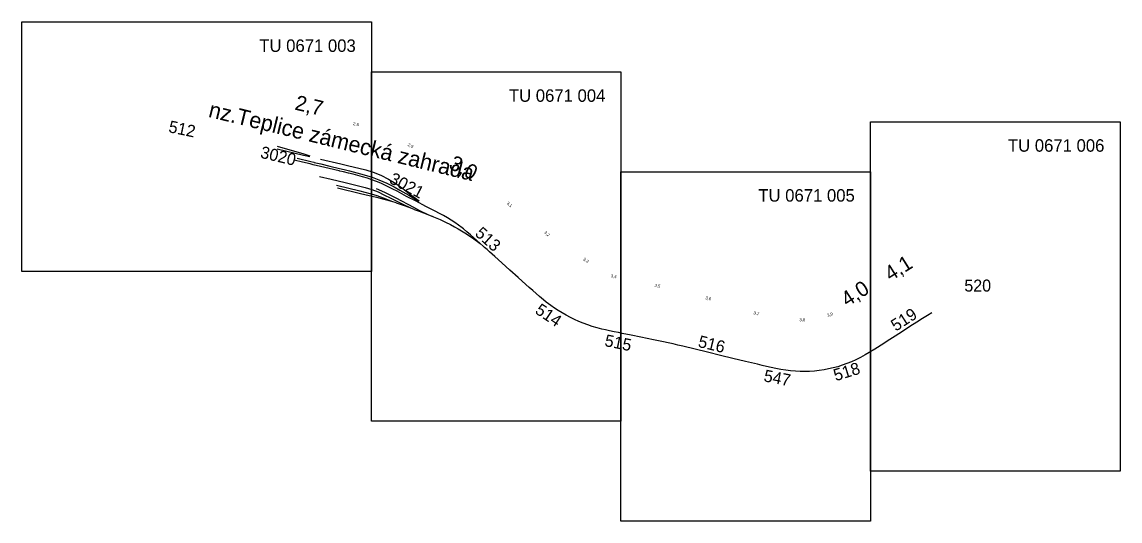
# Model space of a CAD drawing. Extents: x -777700 to -775500, y -977500 to -976500.
import ezdxf

# ---------------------------------------------------------------- set-up
doc = ezdxf.new("R2010")
doc.units = 0
for name, color, linetype in [('Vrstva 1', 7, 'Continuous'), ('Vrstva 23', 7, 'Continuous'), ('Vrstva 61', 7, 'Continuous'), ('Vrstva 63', 7, 'Continuous'), ('Vrstva 7', 7, 'Continuous')]:
    doc.layers.add(name, color=color, linetype=linetype)

msp = doc.modelspace()

# ---------------------------------------------------------------- linework, layer by layer
at = {"layer": 'Vrstva 1'}
for p, q in [((-776950.3, -976862.1), (-776936.5, -976867.2)), ((-776936.5, -976867.2), (-776922.7, -976871.7))]:
    msp.add_line(p, q, dxfattribs=at)
for points in [[(-777188.8, -976749.1), (-777135.1, -976764.4), (-777123.1, -976768.5)], [(-777188.8, -976754), (-777135.9, -976766.6), (-777123.5, -976769.6)], [(-775877.3, -977082.6), (-775886, -977088), (-775895.6, -977094.1), (-775907, -977101.4), (-775921.2, -977110.5), (-775935.9, -977120), (-775950.7, -977129.5), (-775966.3, -977139.5), (-775973.5, -977144.1), (-775991.6, -977155.7), (-776002.5, -977162.5), (-776010.7, -977167.3), (-776019.9, -977172.3), (-776029.2, -977176.9), (-776038.3, -977181), (-776047.2, -977184.6), (-776057, -977188), (-776065.5, -977190.7), (-776074.8, -977193.1), (-776083.9, -977195.2), (-776092.6, -977196.9), (-776102.6, -977198.4), (-776112, -977199.4), (-776122, -977200.2), (-776131.5, -977200.5), (-776140.9, -977200.4), (-776150.3, -977200), (-776160.4, -977199.2), (-776169.7, -977198), (-776179.7, -977196.4), (-776189.6, -977194.5), (-776198.8, -977192.4), (-776208, -977190.3), (-776217.2, -977188.1), (-776226.4, -977185.9), (-776250.7, -977180), (-776275.6, -977174), (-776300.6, -977168), (-776326.2, -977161.8), (-776351.2, -977155.8), (-776376.1, -977149.8), (-776386, -977147.4), (-776395.2, -977145.2), (-776405, -977143), (-776414.9, -977140.8), (-776424.8, -977138.7), (-776434.7, -977136.6), (-776447.4, -977134.1), (-776460, -977131.6), (-776479.2, -977127.7), (-776497.4, -977124.1), (-776505, -977122.5), (-776513.4, -977120.9), (-776522.6, -977119), (-776530.8, -977117.2), (-776538.4, -977115.4), (-776547.6, -977113), (-776557.3, -977110.1), (-776566.3, -977107.1), (-776575.4, -977103.7), (-776584.2, -977100.2), (-776592.8, -977096.3), (-776601.3, -977092.2), (-776609.6, -977087.8), (-776617.9, -977083.1), (-776625.9, -977078.2), (-776633.2, -977073.4), (-776640.7, -977068.1), (-776649.5, -977061.3), (-776655.4, -977056.6), (-776662.8, -977050.3), (-776670, -977044.1), (-776676.6, -977038.2), (-776683.7, -977031.9), (-776690.2, -977026), (-776706.1, -977011.8), (-776722.3, -976997.3), (-776738.5, -976982.7), (-776752.7, -976970), (-776763, -976960.8), (-776768.1, -976956.2), (-776773.3, -976951.6), (-776776.2, -976949), (-776782, -976943.8), (-776795.4, -976931.9), (-776801.4, -976926.5), (-776808.5, -976920.3), (-776815.5, -976914.4), (-776817.9, -976912.6), (-776825.3, -976907), (-776832.5, -976901.9), (-776839.9, -976897.2), (-776847.3, -976892.7), (-776855.3, -976888.1), (-776863.6, -976883.7), (-776872.2, -976879.2), (-776890.6, -976869.6), (-776910.2, -976859.4), (-776929.4, -976849.4), (-776948.6, -976839.3), (-776957, -976835), (-776965.3, -976830.7), (-776973.3, -976826.9), (-776981.2, -976823.3), (-776990, -976819.6), (-776998.8, -976816.2), (-777007.8, -976813.1), (-777017.4, -976810.1), (-777027.2, -976807.4), (-777036.2, -976805.1), (-777045.5, -976802.9), (-777055.5, -976800.5), (-777063, -976798.7), (-777064.8, -976798.3), (-777084.2, -976793.7), (-777102, -976789.5), (-777116.5, -976786), (-777122.3, -976784.6), (-777138, -976780.8), (-777154.5, -976776.9)], [(-777148.9, -976773.2), (-777121.3, -976779.8), (-777115.3, -976781.2), (-777114.4, -976781.4), (-777101.1, -976784.6), (-777083.2, -976788.9), (-777063.6, -976793.6), (-777054.4, -976795.8), (-777043.5, -976798.4), (-777036.1, -976800.3), (-777014.1, -976806.1), (-776998.5, -976811), (-776984.8, -976816.2), (-776969, -976823.3), (-776954.3, -976830.6), (-776942.8, -976836.8), (-776924.8, -976846.8), (-776904.6, -976859)], [(-777102, -976774.8), (-777061.1, -976784.5), (-777047.8, -976787.8), (-777011.3, -976796.6), (-776996.1, -976801.1), (-776981.1, -976807.1), (-776965.7, -976814.8), (-776951, -976823.8), (-776936.9, -976833.8), (-776923.4, -976844.1), (-776904.5, -976858.6)], [(-777103.6, -976809.4), (-777080.8, -976814.9), (-777052.4, -976821.6), (-777030.9, -976826.7), (-777012.3, -976831.6), (-776999.3, -976835.7), (-776986.3, -976840.7), (-776974.7, -976846.1), (-776961, -976852.9), (-776935.9, -976865.7), (-776922.7, -976871.7), (-776914.7, -976875.3), (-776914, -976875.6), (-776904, -976879.3), (-776887.1, -976885.8), (-776878.9, -976889), (-776878.2, -976889.3), (-776875.3, -976890.4), (-776862.1, -976896), (-776850.4, -976901.5), (-776842.6, -976905.4), (-776841.2, -976906.1), (-776833.2, -976910.3), (-776826, -976914.4), (-776819.3, -976918.3), (-776812.9, -976922.3), (-776811.4, -976923.2), (-776804.5, -976927.8), (-776797.2, -976932.8), (-776782, -976943.8), (-776776.2, -976949), (-776773.3, -976951.6)], [(-777069.6, -976827.3), (-777023.3, -976838.5), (-777003, -976843.5), (-776990.7, -976847.3), (-776974.3, -976853.2), (-776959.3, -976858.8), (-776951, -976861.8), (-776950.3, -976862.1)], [(-777067.9, -976832.6), (-777021.7, -976843.7), (-776989.6, -976851.3), (-776974.8, -976854.9), (-776959.3, -976858.8)], [(-776990.5, -976833.5), (-776973.5, -976840.9), (-776951, -976852.2), (-776915.5, -976871.1), (-776903.3, -976877.5), (-776887.1, -976885.8)]]:
    msp.add_lwpolyline(points, dxfattribs=at)
at = {"layer": 'Vrstva 61'}
for points in [[(-777700, -977000), (-777700, -976500), (-777000, -976500), (-777000, -977000), (-777700, -977000)], [(-777000, -977300), (-777000, -976600), (-776500, -976600), (-776500, -977300), (-777000, -977300)], [(-776000, -977400), (-776000, -976700), (-775500, -976700), (-775500, -977400), (-776000, -977400)], [(-776500, -977500), (-776500, -976800), (-776000, -976800), (-776000, -977500), (-776500, -977500)]]:
    msp.add_lwpolyline(points, dxfattribs=at)

# ---------------------------------------------------------------- texts
at = {"layer": 'Vrstva 23'}
msp.add_text('nz.Teplice zámecká zahrada', height=32, rotation=346.3007, dxfattribs=at).set_placement((-777328, -976689.9))
at = {"layer": 'Vrstva 61'}
for s, p in [('TU 0671 003', (-777224.5, -976560)), ('TU 0671 004', (-776724.4, -976660)), ('TU 0671 006', (-775724.6, -976760)), ('TU 0671 005', (-776224.7, -976860))]:
    msp.add_text(s, height=25, dxfattribs=at).set_placement(p)
at = {"layer": 'Vrstva 63'}
for s, rotation, p in [('512', 348.1344, (-777407.7, -976720.6)), ('3020', 346.511, (-777223.9, -976771.7)), ('3021', 332.3914, (-776966, -976821.5)), ('513', 318.2224, (-776794.1, -976926.2)), ('514', 326.4025, (-776673.8, -977082.5)), ('519', 32.6555, (-775949.3, -977120.7)), ('515', 348.5961, (-776534, -977149.2)), ('516', 346.4213, (-776346.8, -977150.9)), ('518', 17.2934, (-776069.7, -977220)), ('547', 348.9167, (-776215.2, -977219.8))]:
    msp.add_text(s, height=24, rotation=rotation, dxfattribs=at).set_placement(p)
msp.add_text('520', height=24, dxfattribs=at).set_placement((-775811.9, -977040.2))
at = {"layer": 'Vrstva 7'}
for s, height, rotation, p in [('2,7', 30, 346.511, (-777154.9, -976675.3)), ('2,8', 6, 346.6442, (-777037, -976706.4)), ('2,9', 6, 333.1228, (-776927.8, -976747.9)), ('3,0', 30, 332.5182, (-776846.8, -976792.3)), ('3,1', 6, 318.2546, (-776729.4, -976863.8)), ('3,2', 6, 318.1107, (-776654.3, -976922.7)), ('3,3', 6, 324.6903, (-776576.2, -976976.6)), ('4,1', 30, 32.0149, (-775960, -977020.4)), ('3,4', 6, 345.3804, (-776520.7, -977011)), ('4,0', 30, 32.8009, (-776046.6, -977071.7)), ('3,5', 6, 348.746, (-776433, -977030.3)), ('3,6', 6, 346.4213, (-776331.2, -977055.3)), ('3,7', 6, 346.3991, (-776234.8, -977085.5)), ('3,9', 6, 17.2934, (-776085.8, -977090.9)), ('3,8', 6, 359.3065, (-776142.3, -977099.6))]:
    msp.add_text(s, height=height, rotation=rotation, dxfattribs=at).set_placement(p)

doc.saveas('drawing.dxf')
